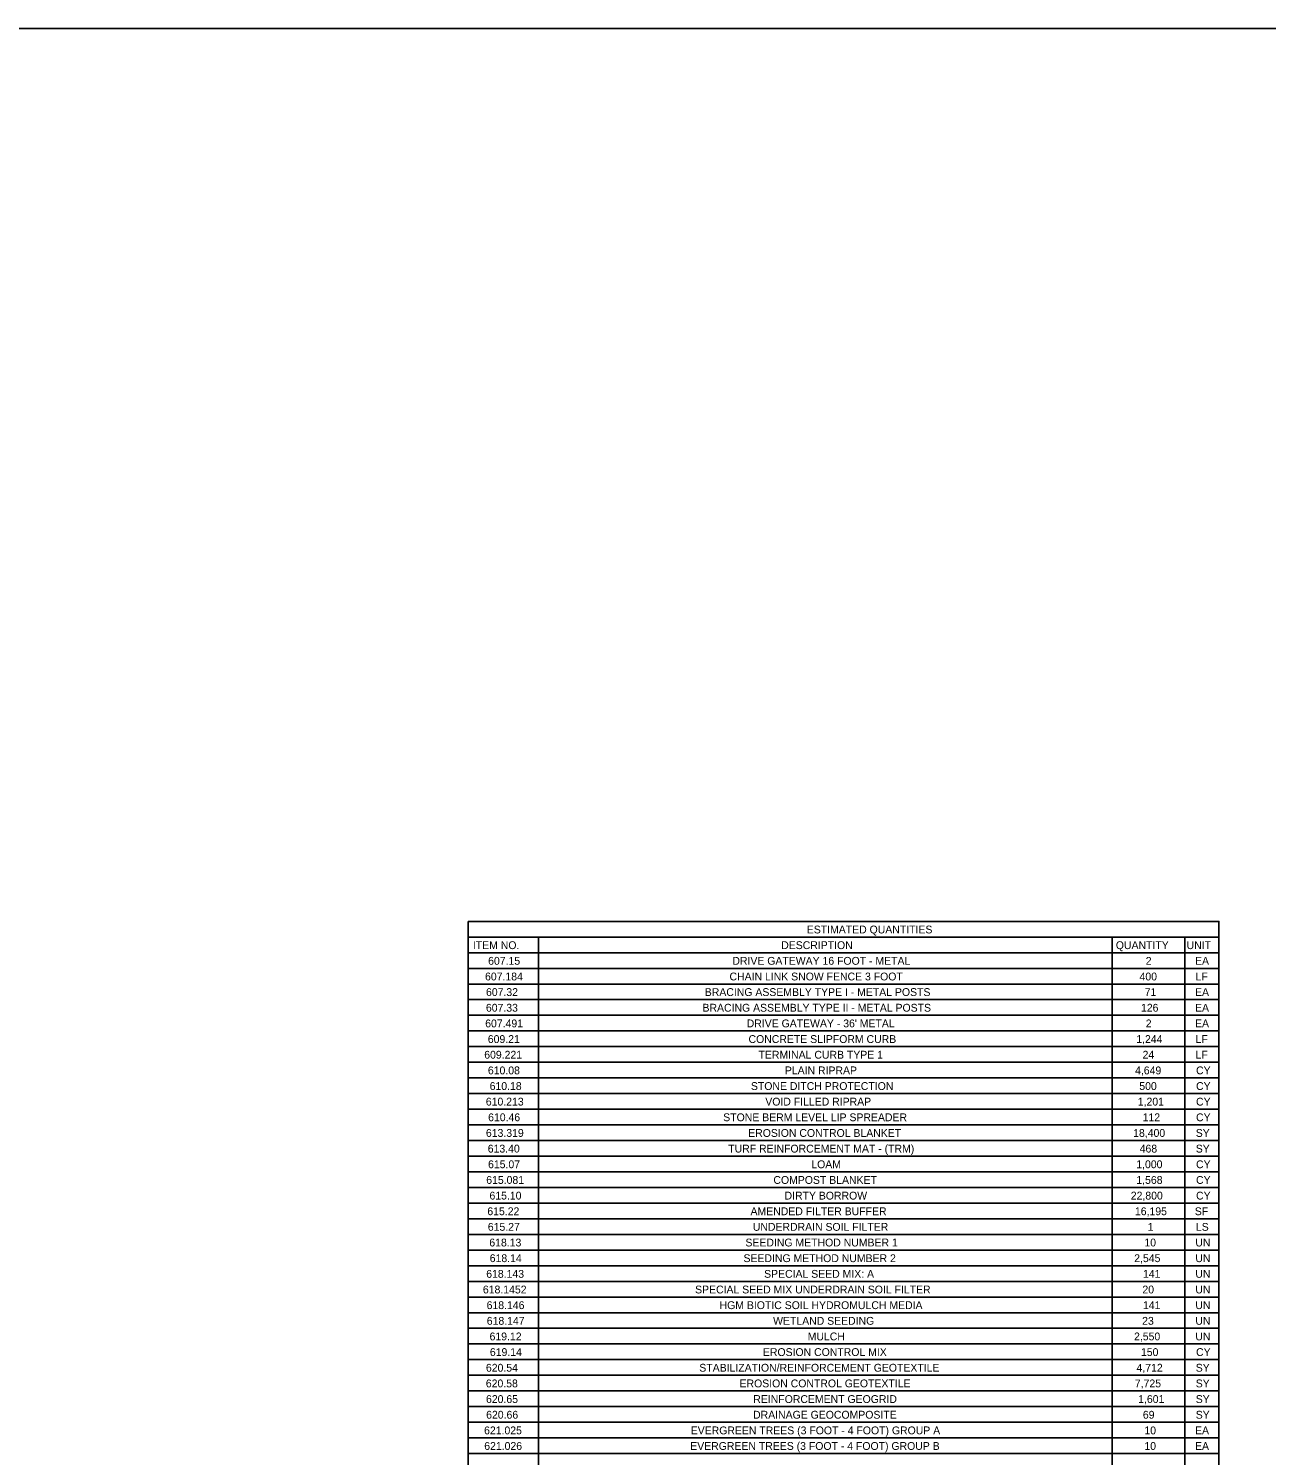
# Model space of a CAD drawing. Extents: x -18.7 to 5.6, y -2.7 to 5.1.
# Drawn here: x -6.783 to -5.226, y 3.303 to 5.098 of the extents above; entities that cross this region are included whole.
import ezdxf

# ---------------------------------------------------------------- set-up
doc = ezdxf.new("R2010")
doc.units = 0
for name, color, linetype in [('ANNOTATION', 7, 'Continuous'), ('BORDER', 7, 'Continuous'), ('Default', 7, 'Continuous')]:
    doc.layers.add(name, color=color, linetype=linetype)

msp = doc.modelspace()

# ---------------------------------------------------------------- linework, layer by layer
at = {"layer": 'BORDER'}
for p, q in [((-6.2304, 3.9551), (-5.2861, 3.9551)), ((-6.1418, 3.9551), (-6.1418, 2.2424)), ((-5.4205, 3.9551), (-5.4205, 2.2424)), ((-5.3291, 3.9551), (-5.3291, 2.2424)), ((-6.2304, 3.9354), (-5.2861, 3.9354)), ((-6.2304, 3.9157), (-5.2861, 3.9157)), ((-6.2304, 3.896), (-5.2861, 3.896)), ((-6.2304, 3.8764), (-5.2861, 3.8764)), ((-6.2304, 3.8567), (-5.2861, 3.8567)), ((-6.2304, 3.837), (-5.2861, 3.837)), ((-6.2304, 3.8173), (-5.2861, 3.8173)), ((-6.2304, 3.7976), (-5.2861, 3.7976)), ((-6.2304, 3.7779), (-5.2861, 3.7779)), ((-6.2304, 3.7582), (-5.2861, 3.7582)), ((-6.2304, 3.7386), (-5.2861, 3.7386)), ((-6.2304, 3.7189), (-5.2861, 3.7189)), ((-6.2304, 3.6992), (-5.2861, 3.6992)), ((-6.2304, 3.6795), (-5.2861, 3.6795)), ((-6.2304, 3.6598), (-5.2861, 3.6598)), ((-6.2304, 3.6401), (-5.2861, 3.6401)), ((-6.2304, 3.6204), (-5.2861, 3.6204)), ((-6.2304, 3.6008), (-5.2861, 3.6008)), ((-6.2304, 3.5811), (-5.2861, 3.5811)), ((-6.2304, 3.5614), (-5.2861, 3.5614)), ((-6.2304, 3.5417), (-5.2861, 3.5417)), ((-6.2304, 3.522), (-5.2861, 3.522)), ((-6.2304, 3.5023), (-5.2861, 3.5023)), ((-6.2304, 3.4826), (-5.2861, 3.4826)), ((-6.2304, 3.463), (-5.2861, 3.463)), ((-6.2304, 3.4433), (-5.2861, 3.4433)), ((-6.2304, 3.4236), (-5.2861, 3.4236)), ((-6.2304, 3.4039), (-5.2861, 3.4039)), ((-6.2304, 3.3842), (-5.2861, 3.3842)), ((-6.2304, 3.3645), (-5.2861, 3.3645)), ((-6.2304, 3.3448), (-5.2861, 3.3448)), ((-6.2304, 3.3251), (-5.2861, 3.3251)), ((-6.2304, 3.3055), (-5.2861, 3.3055))]:
    msp.add_line(p, q, dxfattribs=at)
msp.add_lwpolyline([(-6.2304, 3.9748), (-5.2861, 3.9748), (-5.2861, 2.2424), (-6.2304, 2.2424)], close=True, dxfattribs=at)
at = {"layer": 'Default'}
msp.add_lwpolyline([(-10.8151, 5.0978), (-2.7516, 5.0978), (-2.7516, 1.5028), (-10.8151, 1.5028)], close=True, dxfattribs=at)

# ---------------------------------------------------------------- texts
at = {"layer": 'ANNOTATION'}
for s, height, p in [('607.15', 0.00984, (-6.2053, 3.9203)), ('DRIVE GATEWAY 16 FOOT - METAL', 0.009843, (-5.8981, 3.9203)), ('2', 0.00984, (-5.3782, 3.9203)), ('EA', 0.00984, (-5.3162, 3.9203)), ('607.184', 0.00984, (-6.2092, 3.9006)), ('CHAIN LINK SNOW FENCE 3 FOOT', 0.009843, (-5.9017, 3.9006)), ('400', 0.00984, (-5.386, 3.9006)), ('LF', 0.00984, (-5.3155, 3.9006)), ('607.32', 0.00984, (-6.208, 3.881)), ('BRACING ASSEMBLY TYPE I - METAL POSTS', 0.009843, (-5.9328, 3.881)), ('71', 0.00984, (-5.3795, 3.881)), ('EA', 0.00984, (-5.3162, 3.881)), ('607.33', 0.00984, (-6.2081, 3.8613)), ('BRACING ASSEMBLY TYPE II - METAL POSTS', 0.009843, (-5.9357, 3.8613)), ('126', 0.00984, (-5.3842, 3.8613)), ('EA', 0.00984, (-5.3162, 3.8613)), ('607.491', 0.00984, (-6.209, 3.8416)), ("DRIVE GATEWAY - 36' METAL", 0.009843, (-5.8801, 3.8416)), ('2', 0.00984, (-5.3782, 3.8416)), ('EA', 0.00984, (-5.3162, 3.8416)), ('609.21', 0.00984, (-6.2057, 3.8219)), ('CONCRETE SLIPFORM CURB', 0.009843, (-5.8778, 3.8219)), ('1,244', 0.00984, (-5.3901, 3.8219)), ('LF', 0.00984, (-5.3155, 3.8219)), ('609.221', 0.00984, (-6.2102, 3.8022)), ('TERMINAL CURB TYPE 1', 0.009843, (-5.8652, 3.8022)), ('24', 0.00984, (-5.3822, 3.8022)), ('LF', 0.00984, (-5.3155, 3.8022)), ('610.08', 0.00984, (-6.2056, 3.7825)), ('PLAIN RIPRAP', 0.009843, (-5.8321, 3.7825)), ('4,649', 0.00984, (-5.3916, 3.7825)), ('CY', 0.00984, (-5.3149, 3.7825)), ('610.18', 0.00984, (-6.2034, 3.7628)), ('STONE DITCH PROTECTION', 0.009843, (-5.8748, 3.7628)), ('500', 0.00984, (-5.3863, 3.7628)), ('CY', 0.00984, (-5.3149, 3.7628)), ('610.213', 0.00984, (-6.2082, 3.7432)), ('VOID FILLED RIPRAP', 0.009843, (-5.8567, 3.7432)), ('1,201', 0.00984, (-5.3882, 3.7432)), ('CY', 0.00984, (-5.3149, 3.7432)), ('610.46', 0.00984, (-6.2053, 3.7235)), ('STONE BERM LEVEL LIP SPREADER', 0.009843, (-5.9096, 3.7235)), ('112', 0.00984, (-5.3821, 3.7235)), ('CY', 0.00984, (-5.3149, 3.7235)), ('613.319', 0.00984, (-6.2081, 3.7038)), ('EROSION CONTROL BLANKET', 0.009843, (-5.8782, 3.7038)), ('18,400', 0.00984, (-5.394, 3.7038)), ('SY', 0.00984, (-5.3153, 3.7038)), ('613.40', 0.00984, (-6.2058, 3.6841)), ('TURF REINFORCEMENT MAT - (TRM)', 0.009843, (-5.9033, 3.6841)), ('468', 0.00984, (-5.3858, 3.6841)), ('SY', 0.00984, (-5.3153, 3.6841)), ('615.07', 0.00984, (-6.2054, 3.6644)), ('LOAM', 0.00984, (-5.7988, 3.6644)), ('1,000', 0.00984, (-5.3901, 3.6644)), ('CY', 0.00984, (-5.3149, 3.6644)), ('615.081', 0.00984, (-6.2077, 3.6447)), ('COMPOST BLANKET', 0.009843, (-5.8465, 3.6447)), ('1,568', 0.00984, (-5.39, 3.6447)), ('CY', 0.00984, (-5.3149, 3.6447)), ('615.10', 0.00984, (-6.2036, 3.625)), ('DIRTY BORROW', 0.009843, (-5.8325, 3.625)), ('22,800', 0.00984, (-5.397, 3.625)), ('CY', 0.00984, (-5.3149, 3.625)), ('615.22', 0.00984, (-6.2063, 3.6053)), ('AMENDED FILTER BUFFER ', 0.009843, (-5.8753, 3.6053)), ('16,195', 0.00984, (-5.3918, 3.6053)), ('SF', 0.00984, (-5.3165, 3.6053)), ('615.27', 0.00984, (-6.2057, 3.5857)), ('UNDERDRAIN SOIL FILTER', 0.009843, (-5.8724, 3.5857)), ('1', 0.00984, (-5.3758, 3.5857)), ('LS', 0.00984, (-5.3151, 3.5857)), ('618.13', 0.00984, (-6.2038, 3.566)), ('SEEDING METHOD NUMBER 1', 0.009843, (-5.8817, 3.566)), ('10', 0.00984, (-5.3799, 3.566)), ('UN', 0.00984, (-5.3158, 3.566)), ('618.14', 0.00984, (-6.2033, 3.5463)), ('SEEDING METHOD NUMBER 2', 0.009843, (-5.8841, 3.5463)), ('2,545', 0.00984, (-5.3927, 3.5463)), ('UN', 0.00984, (-5.3158, 3.5463)), ('618.143', 0.00984, (-6.2077, 3.5266)), ('SPECIAL SEED MIX: A', 0.009843, (-5.8582, 3.5266)), ('141', 0.00984, (-5.3817, 3.5266)), ('UN', 0.00984, (-5.3158, 3.5266)), ('618.1452', 0.00984, (-6.2119, 3.5069)), ('SPECIAL SEED MIX UNDERDRAIN SOIL FILTER', 0.009843, (-5.945, 3.5069)), ('20', 0.00984, (-5.3824, 3.5069)), ('UN', 0.00984, (-5.3158, 3.5069)), ('618.146', 0.00984, (-6.2072, 3.4872)), ('HGM BIOTIC SOIL HYDROMULCH MEDIA', 0.009843, (-5.9142, 3.4872)), ('141', 0.00984, (-5.3817, 3.4872)), ('UN', 0.00984, (-5.3158, 3.4872)), ('618.147', 0.00984, (-6.207, 3.4675)), ('WETLAND SEEDING', 0.009843, (-5.8469, 3.4675)), ('23', 0.00984, (-5.3827, 3.4675)), ('UN', 0.00984, (-5.3158, 3.4675)), ('619.12', 0.00984, (-6.2035, 3.4479)), ('MULCH', 0.00984, (-5.8034, 3.4479)), ('2,550', 0.00984, (-5.3929, 3.4479)), ('UN', 0.00984, (-5.3158, 3.4479)), ('619.14', 0.00984, (-6.2031, 3.4282)), ('EROSION CONTROL MIX', 0.009843, (-5.8597, 3.4282)), ('150', 0.00984, (-5.3842, 3.4282)), ('CY', 0.00984, (-5.3149, 3.4282)), ('620.54', 0.00984, (-6.2081, 3.4085)), ('STABILIZATION/REINFORCEMENT GEOTEXTILE', 0.009843, (-5.9397, 3.4085)), ('4,712', 0.00984, (-5.3898, 3.4085)), ('SY', 0.00984, (-5.3153, 3.4085)), ('620.58', 0.00984, (-6.2082, 3.3888)), ('EROSION CONTROL GEOTEXTILE', 0.009843, (-5.8891, 3.3888)), ('7,725', 0.00984, (-5.3919, 3.3888)), ('SY', 0.00984, (-5.3153, 3.3888)), ('620.65', 0.00984, (-6.208, 3.3691)), ('REINFORCEMENT GEOGRID', 0.009843, (-5.8718, 3.3691)), ('1,601', 0.00984, (-5.3877, 3.3691)), ('SY', 0.00984, (-5.3153, 3.3691)), ('620.66', 0.00984, (-6.2078, 3.3494)), ('DRAINAGE GEOCOMPOSITE', 0.009843, (-5.8721, 3.3494)), ('69', 0.00984, (-5.3818, 3.3494)), ('SY', 0.00984, (-5.3153, 3.3494)), ('621.025', 0.00984, (-6.2104, 3.3297)), ('EVERGREEN TREES (3 FOOT - 4 FOOT) GROUP A', 0.009843, (-5.9505, 3.3297)), ('10', 0.00984, (-5.3799, 3.3297)), ('EA', 0.00984, (-5.3162, 3.3297)), ('EVERGREEN TREES (3 FOOT - 4 FOOT) GROUP B', 0.009843, (-5.9511, 3.3101)), ('621.026', 0.00984, (-6.2102, 3.3101)), ('10', 0.00984, (-5.3799, 3.3101)), ('EA', 0.00984, (-5.3162, 3.3101))]:
    msp.add_text(s, height=height, dxfattribs=at).set_placement(p)
at = {"layer": 'BORDER'}
for s, height, p in [('ESTIMATED QUANTITIES', 0.009843, (-5.8045, 3.9597)), ('ITEM NO.', 0.00984, (-6.2245, 3.94)), ('DESCRIPTION', 0.009843, (-5.8367, 3.94)), ('QUANTITY', 0.00984, (-5.4158, 3.94)), ('UNIT', 0.00984, (-5.3268, 3.94))]:
    msp.add_text(s, height=height, dxfattribs=at).set_placement(p)

doc.saveas('drawing.dxf')
